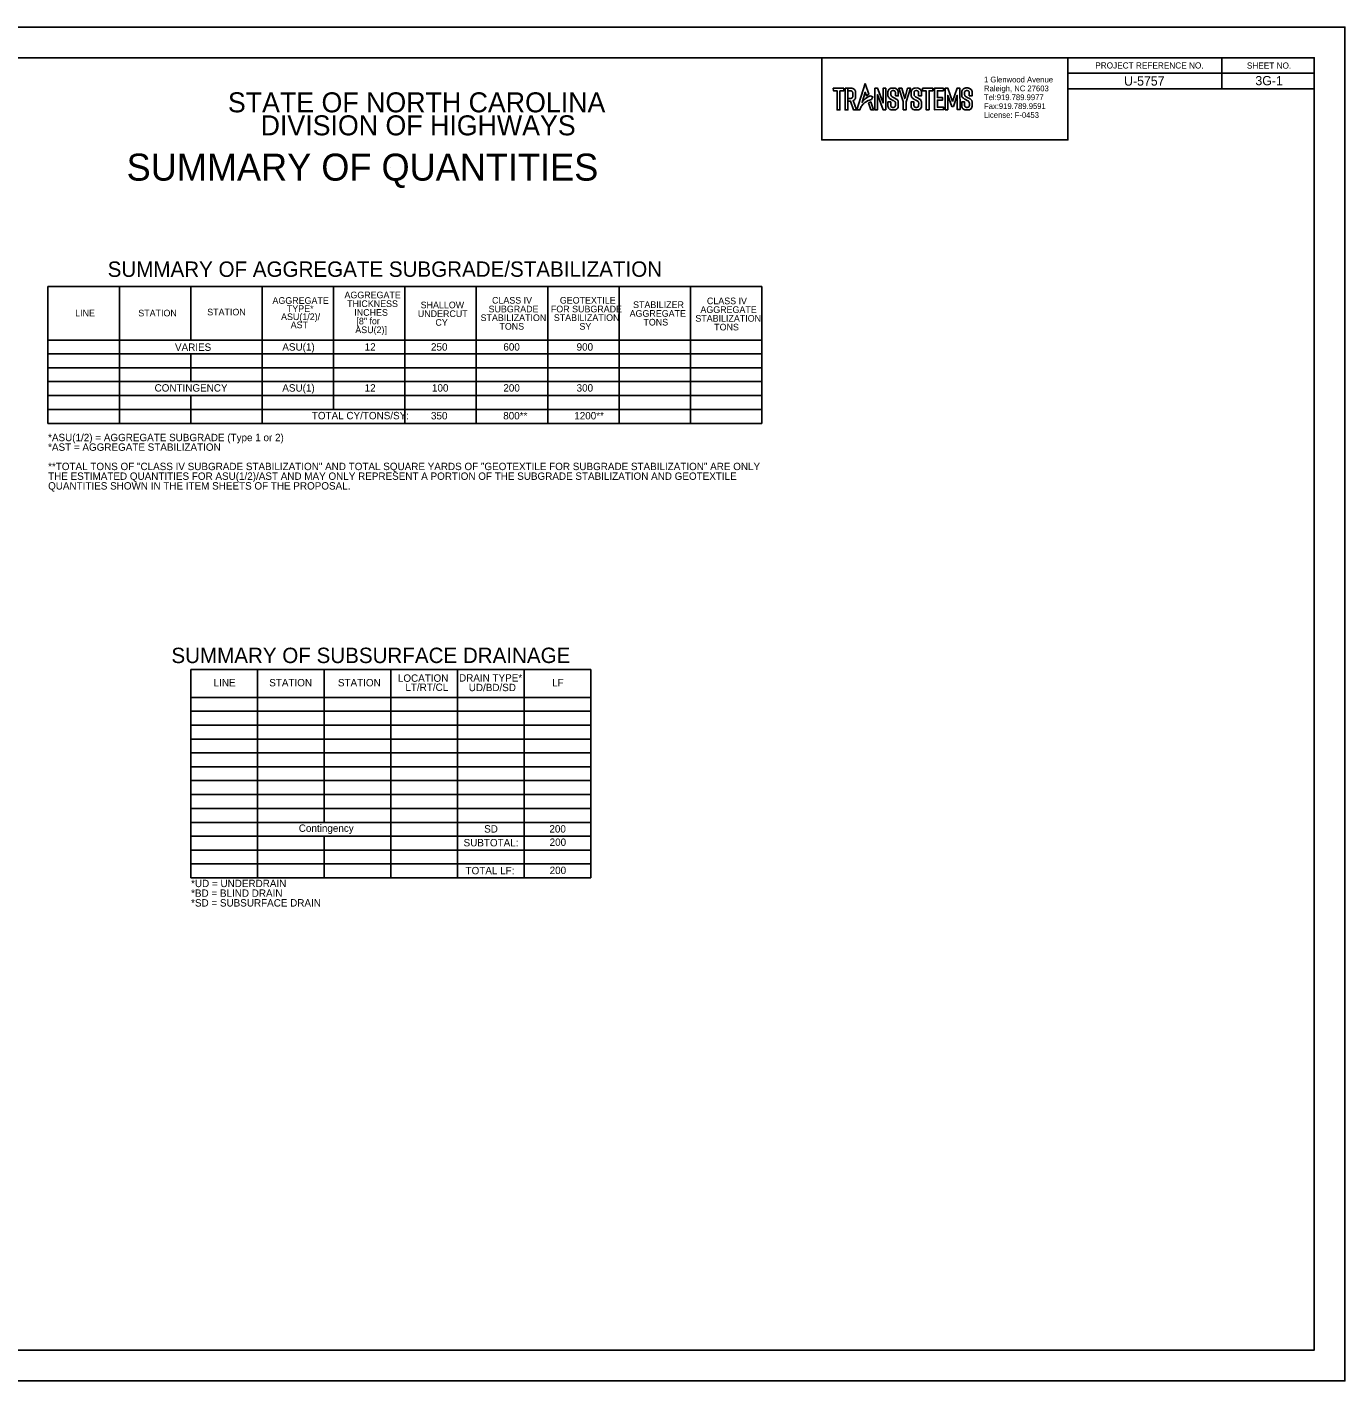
# Model space of a CAD drawing. Extents: x 573680 to 575380, y -54660 to -53560.
# Drawn here: x 574309 to 575380, y -54660 to -53560 of the extents above; entities that cross this region are included whole.
import ezdxf

# ---------------------------------------------------------------- set-up
doc = ezdxf.new("R2010")
doc.units = 0
for name, color, linetype in [('Old_Level_2', 7, 'Continuous'), ('Old_Level_58', 7, 'Continuous'), ('Sheet Data Field CELL', 7, 'Continuous'), ('Sheet Plan And Profile CELL', 7, 'Continuous'), ('Sheet Plot Border Outside CELL', 7, 'Continuous'), ('Sheet Summary CELL', 7, 'Continuous'), ('Sheet Summary Combination CELL', 7, 'Continuous'), ('Sheet Summary Combination Grid CELL', 7, 'Continuous')]:
    doc.layers.add(name, color=color, linetype=linetype)

msp = doc.modelspace()

# ---------------------------------------------------------------- linework, layer by layer
at = {"layer": 'Old_Level_58'}
msp.add_lwpolyline([(574954.8, -53584.7), (575154.8, -53584.7), (575154.8, -53651.4), (574954.8, -53651.4)], close=True, dxfattribs=at)
at = {"layer": 'Sheet Plan And Profile CELL'}
for p, q in [((575279.9, -53584.8), (575279.9, -53609.8)), ((575154.8, -53597.3), (575354.9, -53597.3))]:
    msp.add_line(p, q, dxfattribs=at)
msp.add_lwpolyline([(575354.9, -53584.7), (573854.9, -53584.7), (573854.9, -54634.7), (575354.9, -54634.7)], close=True, dxfattribs=at)
at = {"layer": 'Sheet Plot Border Outside CELL'}
msp.add_lwpolyline([(573679.9, -54659.7), (575379.9, -54659.7), (575379.9, -53559.7), (573679.9, -53559.7)], close=True, dxfattribs=at)
at = {"layer": 'Sheet Summary CELL'}
for p, q in [((575279.9, -53584.8), (575279.9, -53609.8)), ((575154.8, -53597.3), (575354.9, -53597.3)), ((574604.5, -53673.5), (574604.5, -53673.5))]:
    msp.add_line(p, q, dxfattribs=at)
msp.add_lwpolyline([(575154.8, -53584.7), (575354.9, -53584.7), (575354.9, -53609.8), (575154.8, -53609.8)], close=True, dxfattribs=at)
at = {"layer": 'Sheet Summary Combination CELL'}
for p, q in [((574569.8, -54081.8), (574569.8, -54081.8)), ((574575.4, -54081.9), (574575.4, -54081.9)), ((574583.6, -54081.7), (574583.6, -54081.7)), ((574588.6, -54081.8), (574588.6, -54081.8))]:
    msp.add_line(p, q, dxfattribs=at)
at = {"layer": 'Sheet Summary Combination Grid CELL'}
for p, q in [((574326.1, -53770.4), (574326.1, -53881.7)), ((574326.1, -53770.4), (574906.1, -53770.4)), ((574384.1, -53770.4), (574384.1, -53881.7)), ((574442.1, -53770.4), (574442.1, -53814)), ((574500.1, -53770.4), (574500.1, -53881.7)), ((574558.1, -53770.4), (574558.1, -53870.4)), ((574616.1, -53770.4), (574616.1, -53881.7)), ((574674.1, -53770.4), (574674.1, -53881.7)), ((574732.1, -53770.4), (574732.1, -53881.7)), ((574790.1, -53770.4), (574790.1, -53881.7)), ((574848.1, -53770.4), (574848.1, -53881.7)), ((574906.1, -53770.4), (574906.1, -53881.7)), ((574326.1, -53814), (574906.1, -53814)), ((574326.1, -53814), (574906.1, -53814)), ((574326.1, -53825.3), (574906.1, -53825.3)), ((574442.1, -53825.3), (574442.1, -53847.8)), ((574326.1, -53836.6), (574906.1, -53836.6)), ((574326.1, -53847.8), (574906.1, -53847.8)), ((574326.1, -53859.1), (574906.1, -53859.1)), ((574442.1, -53859.1), (574442.1, -53881.7)), ((574326.1, -53870.4), (574906.1, -53870.4)), ((574326.1, -53881.7), (574906.1, -53881.7)), ((574442.3, -54081.8), (574767.2, -54081.8)), ((574442.3, -54081.8), (574442.3, -54251)), ((574496.4, -54081.8), (574496.4, -54251)), ((574550.6, -54081.8), (574550.6, -54205.9)), ((574604.7, -54081.8), (574604.7, -54251)), ((574658.9, -54081.8), (574658.9, -54251)), ((574713, -54081.8), (574713, -54251)), ((574767.2, -54081.8), (574767.2, -54251)), ((574442.3, -54104.4), (574767.2, -54104.4)), ((574442.3, -54115.6), (574767.2, -54115.6)), ((574442.3, -54126.9), (574767.2, -54126.9)), ((574442.3, -54138.2), (574767.2, -54138.2)), ((574442.3, -54149.5), (574696.2, -54149.5)), ((574442.3, -54149.5), (574767.2, -54149.5)), ((574442.3, -54160.8), (574767.2, -54160.8)), ((574442.3, -54172), (574767.2, -54172)), ((574442.3, -54183.3), (574767.2, -54183.3)), ((574442.3, -54194.6), (574767.2, -54194.6)), ((574442.3, -54205.9), (574767.2, -54205.9)), ((574442.3, -54217.2), (574767.2, -54217.2)), ((574550.6, -54217.2), (574550.6, -54251)), ((574442.3, -54228.5), (574767.2, -54228.5)), ((574442.3, -54239.7), (574767.2, -54239.7)), ((574442.3, -54251), (574767.2, -54251))]:
    msp.add_line(p, q, dxfattribs=at)
for points in [[(574964.1, -53609.5), (574972.6, -53609.5), (574972.6, -53611.6), (574969.5, -53611.6), (574969.5, -53627), (574967.2, -53627), (574967.2, -53611.5), (574964.2, -53611.5)], [(574973.8, -53609.5), (574976.1, -53609.5), (574976.1, -53627.1), (574973.8, -53627.1)], [(574976.1, -53611.6), (574978.5, -53611.6), (574978.8, -53611.6), (574979.2, -53611.8), (574979.5, -53612), (574979.7, -53612.3), (574979.9, -53612.6), (574980, -53612.9), (574980, -53613.5), (574980, -53615.9), (574980, -53616.3), (574979.9, -53616.7), (574979.7, -53617), (574979.5, -53617.3), (574979.3, -53617.5), (574978.9, -53617.6), (574978.5, -53617.7), (574978.2, -53617.7), (574976.1, -53617.7), (574976.1, -53619.8), (574978.2, -53619.8), (574980.6, -53627), (574983, -53627), (574980.3, -53619.4), (574980.7, -53619.3), (574981.3, -53618.9), (574981.7, -53618.4), (574982.1, -53617.7), (574982.3, -53617.1), (574982.3, -53616.9), (574982.3, -53612.3), (574982.1, -53611.6), (574981.8, -53610.9), (574981.4, -53610.4), (574980.7, -53610), (574980, -53609.7), (574979.3, -53609.5), (574978.9, -53609.5), (574976.1, -53609.5)], [(574990.1, -53605.6), (574983.4, -53627), (574985.7, -53627), (574986, -53626.1), (574986.6, -53625), (574986.9, -53624.3), (574987.3, -53623.8), (574987.8, -53623), (574988.1, -53622.6), (574988.5, -53622.2), (574988.9, -53621.8), (574989.4, -53621.3), (574989.8, -53621), (574990.2, -53620.7), (574990.8, -53620.4), (574991.2, -53620.1), (574992.5, -53619.5), (574993.5, -53619.1), (574995.1, -53618.5), (574996.2, -53616.4), (574994.1, -53615.5), (574992.4, -53616.3), (574991.1, -53617.2), (574990.1, -53618), (574989.6, -53618.5), (574989, -53619), (574988.5, -53619.6), (574988.1, -53620), (574987.7, -53620.7), (574987.5, -53621), (574990.1, -53612.7), (574991.1, -53615.5), (574993, -53614.3)], [(574997.9, -53609.5), (574997.9, -53626.9), (575000.1, -53626.9), (575000.1, -53614.6), (575004.6, -53626.9), (575006.8, -53626.9), (575006.8, -53609.4), (575004.6, -53609.4), (575004.6, -53621.4), (575000.2, -53609.5)], [(575014.6, -53615.6), (575016.9, -53615.6), (575016.9, -53612.2), (575016.7, -53611.4), (575016.4, -53610.9), (575016.1, -53610.5), (575015.7, -53610.1), (575015.3, -53609.8), (575014.9, -53609.7), (575014.9, -53609.7), (575014.4, -53609.5), (575013.9, -53609.3), (575013.6, -53609.3), (575011.9, -53609.3), (575011.3, -53609.4), (575010.9, -53609.5), (575010.4, -53609.7), (575010, -53609.9), (575009.6, -53610.2), (575009.3, -53610.5), (575009.1, -53610.9), (575008.9, -53611.3), (575008.6, -53612), (575008.6, -53612.5), (575008.6, -53615.7), (575008.7, -53616.1), (575008.9, -53616.6), (575009.2, -53617), (575009.5, -53617.3), (575009.9, -53617.7), (575010.4, -53618), (575010.7, -53618.3), (575011.2, -53618.5), (575011.7, -53618.7), (575012, -53619), (575012.5, -53619.3), (575013, -53619.5), (575013.4, -53619.7), (575013.9, -53620.1), (575014.2, -53620.3), (575014.4, -53620.6), (575014.6, -53621.1), (575014.7, -53621.4), (575014.6, -53623.6), (575014.5, -53624.1), (575014.2, -53624.5), (575013.9, -53624.8), (575013.6, -53625), (575013.2, -53625), (575012.3, -53625.1), (575011.9, -53625), (575011.6, -53624.8), (575011.3, -53624.6), (575011.1, -53624.2), (575011, -53623.9), (575010.9, -53623.6), (575010.8, -53620.5), (575008.5, -53620.6), (575008.5, -53624.3), (575008.7, -53624.5), (575008.9, -53625.4), (575009.1, -53625.7), (575009.4, -53626), (575009.7, -53626.4), (575010, -53626.6), (575010.5, -53626.8), (575010.6, -53626.8), (575011.1, -53627), (575011.6, -53627.1), (575012, -53627.1), (575014.1, -53627.1), (575014.7, -53626.9), (575015.6, -53626.5), (575015.8, -53626.4), (575016.5, -53625.6), (575016.8, -53624.8), (575016.9, -53624.1), (575016.9, -53620.7), (575016.9, -53620.2), (575016.8, -53619.9), (575016.6, -53619.5), (575016, -53618.7), (575015.3, -53618.2), (575014.3, -53617.6), (575013.6, -53617.2), (575012.1, -53616.4), (575011.4, -53615.8), (575011.1, -53615.4), (575011, -53615.1), (575010.9, -53614.8), (575010.9, -53612.4), (575011.1, -53612.2), (575011.2, -53611.9), (575011.4, -53611.8), (575011.6, -53611.6), (575011.9, -53611.4), (575012.1, -53611.3), (575012.3, -53611.4), (575012.3, -53611.3), (575013.2, -53611.3), (575013.5, -53611.4), (575013.8, -53611.5), (575014.1, -53611.6), (575014.2, -53611.8), (575014.4, -53612.1), (575014.5, -53612.4), (575014.6, -53612.7), (575014.6, -53613)], [(575019.9, -53609.5), (575017.3, -53609.5), (575020.9, -53620.3), (575021, -53626.9), (575023.4, -53626.9), (575023.3, -53620.4), (575027, -53609.4), (575024.5, -53609.5), (575022.2, -53617.8)], [(575033.5, -53615.6), (575035.8, -53615.6), (575035.8, -53612.1), (575035.6, -53611.4), (575035.3, -53610.8), (575035, -53610.4), (575034.6, -53610.1), (575034.2, -53609.8), (575033.7, -53609.6), (575033.7, -53609.6), (575033.3, -53609.4), (575032.8, -53609.3), (575032.5, -53609.2), (575030.7, -53609.3), (575030.2, -53609.4), (575029.8, -53609.5), (575029.3, -53609.7), (575028.9, -53609.9), (575028.5, -53610.2), (575028.2, -53610.5), (575027.9, -53610.9), (575027.7, -53611.3), (575027.5, -53612), (575027.4, -53612.5), (575027.4, -53615.6), (575027.6, -53616.1), (575027.8, -53616.6), (575028.1, -53617), (575028.4, -53617.3), (575028.8, -53617.7), (575029.3, -53618), (575029.6, -53618.2), (575030, -53618.5), (575030.5, -53618.7), (575030.9, -53619), (575031.4, -53619.2), (575031.9, -53619.5), (575032.3, -53619.7), (575032.7, -53620), (575033.1, -53620.3), (575033.3, -53620.6), (575033.5, -53621.1), (575033.6, -53621.3), (575033.5, -53623.6), (575033.4, -53624.1), (575033.1, -53624.5), (575032.8, -53624.8), (575032.4, -53624.9), (575032.1, -53625), (575031.1, -53625), (575030.8, -53624.9), (575030.5, -53624.8), (575030.1, -53624.6), (575030, -53624.2), (575029.9, -53623.9), (575029.7, -53623.6), (575029.7, -53620.5), (575027.4, -53620.5), (575027.4, -53624.2), (575027.5, -53624.5), (575027.8, -53625.4), (575028, -53625.7), (575028.2, -53626), (575028.6, -53626.4), (575028.9, -53626.6), (575029.4, -53626.8), (575029.5, -53626.8), (575029.9, -53627), (575030.5, -53627.1), (575030.9, -53627.1), (575033, -53627), (575033.6, -53626.9), (575034.4, -53626.5), (575034.7, -53626.4), (575035.3, -53625.6), (575035.7, -53624.8), (575035.8, -53624.1), (575035.8, -53620.7), (575035.8, -53620.2), (575035.6, -53619.8), (575035.4, -53619.5), (575034.9, -53618.7), (575034.2, -53618.2), (575033.2, -53617.6), (575032.5, -53617.1), (575031, -53616.4), (575030.3, -53615.8), (575029.9, -53615.4), (575029.8, -53615.1), (575029.8, -53614.8), (575029.8, -53612.4), (575029.9, -53612.1), (575030.1, -53611.9), (575030.2, -53611.7), (575030.5, -53611.5), (575030.7, -53611.4), (575031, -53611.3), (575031.1, -53611.4), (575031.2, -53611.3), (575032.1, -53611.3), (575032.4, -53611.4), (575032.7, -53611.5), (575032.9, -53611.6), (575033.1, -53611.8), (575033.3, -53612.1), (575033.4, -53612.4), (575033.4, -53612.6), (575033.4, -53612.9)], [(575036.6, -53609.4), (575045.1, -53609.4), (575045.1, -53611.5), (575042, -53611.5), (575042, -53626.9), (575039.6, -53626.9), (575039.6, -53611.4), (575036.6, -53611.4)], [(575053.7, -53609.4), (575046.3, -53609.4), (575046.3, -53626.9), (575053.8, -53626.8), (575053.8, -53624.9), (575048.7, -53624.9), (575048.7, -53619), (575052.9, -53619), (575052.9, -53617), (575048.7, -53617), (575048.7, -53611.5), (575053.7, -53611.5)], [(575061.1, -53620.3), (575057.2, -53609.3), (575055, -53609.5), (575055.1, -53626.9), (575057.2, -53626.9), (575057.2, -53615.2), (575060.4, -53624.2), (575061.8, -53624.2), (575064.9, -53615.1), (575064.9, -53626.8), (575067.2, -53626.8), (575067.1, -53609.4), (575064.8, -53609.4)], [(575074.6, -53615.6), (575076.9, -53615.6), (575076.9, -53612.1), (575076.7, -53611.4), (575076.4, -53610.8), (575076.1, -53610.4), (575075.7, -53610.1), (575075.3, -53609.8), (575074.9, -53609.6), (575074.9, -53609.6), (575074.4, -53609.4), (575073.9, -53609.3), (575073.6, -53609.2), (575071.9, -53609.2), (575071.3, -53609.3), (575070.9, -53609.4), (575070.4, -53609.7), (575070, -53609.9), (575069.6, -53610.1), (575069.3, -53610.5), (575069.1, -53610.8), (575068.9, -53611.2), (575068.6, -53611.9), (575068.6, -53612.4), (575068.6, -53615.6), (575068.7, -53616.1), (575068.9, -53616.6), (575069.2, -53617), (575069.5, -53617.3), (575070, -53617.6), (575070.4, -53618), (575070.7, -53618.2), (575071.2, -53618.4), (575071.7, -53618.7), (575072, -53618.9), (575072.5, -53619.2), (575073, -53619.5), (575073.4, -53619.7), (575073.9, -53620), (575074.2, -53620.3), (575074.4, -53620.5), (575074.6, -53621), (575074.7, -53621.3), (575074.7, -53623.5), (575074.5, -53624), (575074.2, -53624.5), (575073.9, -53624.7), (575073.6, -53624.9), (575073.2, -53625), (575072.3, -53625), (575071.9, -53624.9), (575071.6, -53624.7), (575071.3, -53624.5), (575071.1, -53624.2), (575071, -53623.8), (575070.9, -53623.6), (575070.8, -53620.5), (575068.5, -53620.5), (575068.5, -53624.2), (575068.7, -53624.5), (575068.9, -53625.4), (575069.1, -53625.6), (575069.4, -53626), (575069.7, -53626.3), (575070.1, -53626.5), (575070.5, -53626.7), (575070.6, -53626.8), (575071.1, -53627), (575071.6, -53627), (575072, -53627.1), (575074.1, -53627), (575074.7, -53626.9), (575075.6, -53626.5), (575075.8, -53626.4), (575076.5, -53625.6), (575076.8, -53624.8), (575077, -53624.1), (575076.9, -53620.6), (575076.9, -53620.2), (575076.8, -53619.8), (575076.6, -53619.4), (575076, -53618.7), (575075.3, -53618.1), (575074.3, -53617.5), (575073.6, -53617.1), (575072.1, -53616.3), (575071.4, -53615.8), (575071.1, -53615.4), (575071, -53615.1), (575070.9, -53614.8), (575070.9, -53612.4), (575071.1, -53612.1), (575071.2, -53611.8), (575071.4, -53611.7), (575071.6, -53611.5), (575071.9, -53611.4), (575072.1, -53611.3), (575072.3, -53611.3), (575072.3, -53611.2), (575073.2, -53611.3), (575073.5, -53611.4), (575073.8, -53611.5), (575074.1, -53611.6), (575074.2, -53611.8), (575074.4, -53612.1), (575074.5, -53612.3), (575074.6, -53612.6), (575074.6, -53612.9)], [(574992.7, -53621.3), (574994.6, -53620.6), (574996.9, -53627), (574994.8, -53626.9)]]:
    msp.add_lwpolyline(points, close=True, dxfattribs=at)

# ---------------------------------------------------------------- texts
at = {"layer": 'Old_Level_2'}
for s, p in [('1 Glenwood Avenue', (575086.6, -53604.7)), ('Raleigh, NC 27603', (575086.6, -53611.9)), ('Tel:919.789.9977 ', (575086.6, -53619.1)), ('Fax:919.789.9591', (575086.6, -53626.3)), ('License: F-0453', (575086.6, -53633.5))]:
    msp.add_text(s, height=4.658, rotation=360, dxfattribs=at).set_placement(p)
at = {"layer": 'Sheet Data Field CELL'}
for s, p in [('U-5757', (575200.4, -53607.3)), ('3G-1', (575307.1, -53607))]:
    msp.add_text(s, height=7.5, dxfattribs=at).set_placement(p)
at = {"layer": 'Sheet Plan And Profile CELL'}
for s, p in [('PROJECT REFERENCE NO.', (575177, -53593.4)), ('SHEET NO.', (575300.2, -53593.5))]:
    msp.add_text(s, height=5, rotation=360, dxfattribs=at).set_placement(p)
at = {"layer": 'Sheet Summary CELL'}
for s, height, p in [('PROJECT REFERENCE NO.', 5, (575177, -53593.4)), ('SHEET NO.', 5, (575300.2, -53593.5)), ('STATE OF NORTH CAROLINA', 16.25, (574472.3, -53629)), ('DIVISION OF HIGHWAYS', 16.25, (574498.9, -53647.7)), ('SUMMARY OF QUANTITIES', 21.95, (574390, -53684.5))]:
    msp.add_text(s, height=height, dxfattribs=at).set_placement(p)
at = {"layer": 'Sheet Summary Combination CELL'}
for s, p in [('SUMMARY OF AGGREGATE SUBGRADE/STABILIZATION', (574374.6, -53762.7)), ('SUMMARY OF SUBSURFACE DRAINAGE', (574426.4, -54076.5))]:
    msp.add_text(s, height=12.5, rotation=0.0119, dxfattribs=at).set_placement(p)
for s, height, p in [('LINE', 5.4, (574348.2, -53794.8)), ('STATION', 5.4, (574399.5, -53794.8)), ('STATION', 5.4, (574455.5, -53794)), ('AGGREGATE', 5.4, (574508.5, -53784.6)), ('TYPE*', 5.4, (574520.2, -53791.2)), ('ASU(1/2)/', 5.4, (574515.5, -53797.8)), ('AST', 5.4, (574523.3, -53804.4)), ('VARIES', 6, (574429.3, -53822.8)), ('ASU(1)', 6, (574516.5, -53822.6)), ('12', 6, (574583.4, -53822.6)), ('250', 6, (574637.3, -53822.6)), ('600', 6, (574696.1, -53822.6)), ('900', 6, (574755.6, -53822.6)), ('CONTINGENCY', 6, (574412.7, -53855.9)), ('ASU(1)', 6, (574516.5, -53855.9)), ('12', 6, (574583.4, -53855.9)), ('100', 6, (574638.1, -53855.9)), ('200', 6, (574696.1, -53855.9)), ('300', 6, (574755.6, -53855.9)), ('TOTAL CY/TONS/SY:', 6, (574540.5, -53878.4)), ('350', 6, (574637.3, -53878.5)), ('800**', 6, (574696, -53878.5)), ('1200**', 6, (574753.7, -53878.5)), ('*ASU(1/2) = AGGREGATE SUBGRADE (Type 1 or 2)', 6, (574326.2, -53896.2)), ('*AST = AGGREGATE STABILIZATION', 6, (574326.2, -53904)), ('**TOTAL TONS OF "CLASS IV SUBGRADE STABILIZATION" AND TOTAL SQUARE YARDS OF "GEOTEXTILE FOR SUBGRADE STABILIZATION" ARE ONLY', 6, (574326.2, -53919.7)), ('THE ESTIMATED QUANTITIES FOR ASU(1/2)/AST AND MAY ONLY REPRESENT A PORTION OF THE SUBGRADE STABILIZATION AND GEOTEXTILE', 6, (574326.2, -53927.6)), ('QUANTITIES SHOWN IN THE ITEM SHEETS OF THE PROPOSAL.', 6, (574326.2, -53935.5)), ('LOCATION', 6, (574610.4, -54091.7)), ('LINE', 6, (574460.7, -54095.4)), ('STATION', 6, (574505.9, -54095.4)), ('STATION', 6, (574561.7, -54095.4)), ('LT/RT/CL', 6, (574616.5, -54099.1)), ('Contingency', 6, (574529.9, -54213.6)), ('SD', 6, (574680.5, -54214.2)), ('200', 6, (574733.5, -54214.2)), ('200', 6, (574733.7, -54225)), ('SUBTOTAL:', 6, (574663.8, -54225.4)), ('TOTAL LF:', 6, (574665.4, -54248.1)), ('200', 6, (574733.7, -54247.9)), ('*UD = UNDERDRAIN', 6, (574442.4, -54258.5)), ('*BD = BLIND DRAIN', 6, (574442.4, -54266.4)), ('*SD = SUBSURFACE DRAIN', 6, (574442.4, -54274.3))]:
    msp.add_text(s, height=height, dxfattribs=at).set_placement(p)
at = {"layer": 'Sheet Summary Combination Grid CELL'}
for s, height, p in [('AGGREGATE', 5.4, (574567, -53780.1)), ('CLASS IV', 5.4, (574686.9, -53784.4)), ('GEOTEXTILE', 5.4, (574742, -53784.4)), ('THICKNESS', 5.4, (574569.1, -53787.2)), ('INCHES', 5.4, (574575, -53794.3)), ('UNDERCUT', 5.4, (574626.6, -53795.3)), ('SHALLOW', 5.4, (574628.9, -53788.2)), ('SUBGRADE', 5.4, (574684.1, -53791.5)), ('FOR SUBGRADE', 5.4, (574734.7, -53791.5)), ('AGGREGATE', 5.4, (574798.7, -53795.1)), ('STABILIZER', 5.4, (574801.5, -53788)), ('AGGREGATE', 5.4, (574856.2, -53792)), ('CLASS IV', 5.4, (574861.5, -53784.9)), ('[8" for', 5.4, (574576.7, -53801.3)), ('CY', 5.4, (574640.9, -53802.4)), ('STABILIZATION', 5.4, (574677.6, -53798.6)), ('TONS', 5.4, (574692.9, -53805.6)), ('STABILIZATION', 5.4, (574737.1, -53798.5)), ('SY', 5.4, (574757.9, -53805.6)), ('TONS', 5.4, (574809.9, -53802.2)), ('STABILIZATION', 5.4, (574852.1, -53799.1)), ('TONS', 5.4, (574867.4, -53806.2)), ('ASU(2)]', 5.4, (574575.8, -53808.4)), ('DRAIN TYPE*', 6, (574660.1, -54091.5)), ('UD/BD/SD', 6, (574668, -54099.3)), ('LF', 6, (574735.7, -54095.4))]:
    msp.add_text(s, height=height, dxfattribs=at).set_placement(p)

doc.saveas('drawing.dxf')
